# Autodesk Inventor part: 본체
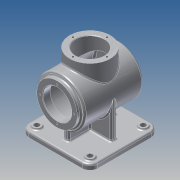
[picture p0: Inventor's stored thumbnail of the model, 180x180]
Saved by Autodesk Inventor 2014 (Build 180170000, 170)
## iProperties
Created: 2015-07
Part Number: 본체
Material: Aluminum 6061
Document SubType Name: Modeling
Designer: user
Density: 2.71 g/cm^3
Appearance: Aluminum - Flat
Mass: 1277.17 g
Surface Area: 1268.79 cm^2
Volume: 471.282 cm^3
Author: user
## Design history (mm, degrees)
sketch "Sketch1"
  geometry: C1 r 45 at (0, 0); 1 further point
  constraints: 1 centre point, 1 coincident
  dimensions: "d0" = 90 diameter of C1
extrude "Extrusion1" new body sketch "Sketch1" distance "d1" = 110; taper "d2" = 0 deg
workplane "Work Plane1"
sketch "Sketch4"
  geometry: L1 (45, 110)-(-45, 110) reference; L2 (-45, 0)-(45, 0) reference; L3 (45, 110)-(-45, 110) reference; L4 (-45, 0)-(45, 0) reference; L5 (-45, 0)-(-45, 110) reference; L6 (45, 0)-(45, 110) reference; L7 (0, 110)-(0, 0); C1 r 38 at (0, 55)
  constraints: 2 end point, 2 midpoint, 1 centre point
  dimensions: "d10" = 76 diameter of C1
extrude "Extrusion4" join sketch "Sketch4" stored distance "d11" = 96; taper "d12" = 0 deg
sketch "Sketch5"
  geometry: C1 r 38 at (0, 0) reference; C2 r 27 at (0, 0); 1 further point
  constraints: 1 centre point, 1 coincident
  dimensions: "d13" = 54 diameter of C2
extrude "Extrusion5" cut sketch "Sketch5" distance "d14" = 50.5; taper "d15" = 0 deg
sketch "Sketch6"
  geometry: C1 r 45 at (0, 0) reference; C2 r 38 at (0, 0)
  constraints: 1 centre point, 1 coincident
  dimensions: "d16" = 76 diameter of C2
extrude "Extrusion6" join sketch "Sketch6" distance "d17" = 7; taper "d18" = 0 deg
sketch "Sketch7"
  geometry: C1 r 38 at (0, 0) reference; C2 r 27 at (0, 0)
  constraints: 1 centre point, 1 coincident
  dimensions: "d19" = 54 diameter of C2
extrude "Extrusion7" cut sketch "Sketch7" distance "d20" = 14; taper "d21" = 0 deg
sketch "Sketch8"
  geometry: C1 r 27 at (0, 0) reference; C2 r 40 at (0, 0)
  constraints: 1 centre point, 1 coincident
  dimensions: "d22" = 80 diameter of C2
extrude "Extrusion8" cut sketch "Sketch8" distance "d23" = 96; taper "d24" = 0 deg
workplane "Work Plane2"
sketch "Sketch9"
  geometry: L1 (65, 120)-(-65, 120); L2 (-65, 120)-(-65, -10); L3 (-65, -10)-(65, -10); L4 (65, -10)-(65, 120); L5 (-45, 0)-(45, 0) reference; L6 (-65, 55)-(65, 55); L7 (45, 110)-(-45, 110) reference; L8 (0, 0)-(0, 110); 1 further point
  constraints: 12 end point, 5 midpoint, 1 parallel
  dimensions: "d26" = 130 distance of L1.start L1.end; "d27" = 130 distance of L1.end L2.end; "d28" = 10 distance between parallel lines of L5 L3; "d29" = 65 distance from line of point (0, 55) L2
extrude "Extrusion9" join sketch "Sketch9" distance "d30" = 10; taper "d31" = 0 deg
sketch "Sketch10"
  geometry: L1 (65, -120)-(65, 10) reference; L2 (65, 10)-(-65, 10) reference; L3 (-65, 10)-(-65, -120) reference; L4 (-65, -120)-(65, -120) reference; L5 (0, -120)-(0, 10); L6 (-65, -55)-(65, -55); L7 (-45, -60)-(45, -60); L8 (-45, -50)-(45, -50); L9 (-5, -100)-(-5, -10); L10 (5, -100)-(5, -10); L11 (-45, -60)-(-45, -50); L12 (-5, -100)-(5, -100); L13 (45, -60)-(45, -50); L14 (-5, -10)-(5, -10); 3 further points
  constraints: 20 end point, 7 parallel, 6 midpoint, 2 point on line
  dimensions: "d34" = 5 distance between parallel lines of L8 L6; "d35" = 10 distance between parallel lines of L8 L7; "d37" = 90 distance of L9.start L9.end; "d38" = 5 distance between parallel lines of L9 L5; "d39" = 10 distance between parallel lines of L10 L9; "d40" = 90 distance between parallel lines of L13 L11
extrude "Extrusion10" join sketch "Sketch10" stored distance "d41" = 10; taper "d42" = 0 deg
sketch "Sketch11"
  geometry: L1 (65, -120)-(65, 10) reference; L2 (65, 10)-(-65, 10) reference; L3 (-65, 10)-(-65, -120) reference; L4 (-65, -120)-(65, -120) reference; L5 (-65, -55)-(65, -55); L6 (0, -120)-(0, 10); C1 r 7.5 at (-50, -105); C2 r 7.5 at (-50, -5); C3 r 7.5 at (50, -105); C4 r 7.5 at (50, -5); 1 further point
  constraints: 4 centre point, 4 end point, 4 midpoint
  dimensions: "d43" = 15 diameter of C1; "d44" = 15 diameter of C2; "d45" = 50 distance from line of L5 C1.centre; "d46" = 100 distance of C2.centre C1.centre; "d47" = 50 distance from line of L6 C1.centre; "d48" = 50 distance from line of L6 C2.centre; "d49" = 50 distance from line of C3.centre L6; "d50" = 50 distance from line of C4.centre L6; "d51" = 50 distance from line of L5 C3.centre; "d52" = 100 distance of C4.centre C3.centre; "d53" = 15 diameter of C3; "d54" = 15 diameter of C4
extrude "Extrusion11" join sketch "Sketch11" distance "d55" = 3; taper "d56" = 0 deg
sketch "Sketch12"
  geometry: C1 r 7.5 at (0, 0) reference; C2 r 5 at (0, 0); 1 further point
  constraints: 1 centre point, 1 coincident
  dimensions: "d57" = 10 diameter of C2
extrude "Extrusion12" cut sketch "Sketch12" distance "d58" = 75.5; taper "d59" = 0 deg
sketch "Sketch13"
  geometry: C1 r 7.5 at (0, 0) reference; C2 r 5 at (0, 0); 1 further point
  constraints: 1 centre point, 1 coincident
  dimensions: "d60" = 10 diameter of C2
extrude "Extrusion13" cut sketch "Sketch13" distance "d61" = 75.5; taper "d62" = 0 deg
sketch "Sketch14"
  geometry: C1 r 7.5 at (0, 0) reference; C2 r 5 at (0, 0); 1 further point
  constraints: 1 centre point, 1 coincident
  dimensions: "d63" = 10 diameter of C2
extrude "Extrusion14" cut sketch "Sketch14" distance "d64" = 75.5; taper "d65" = 0 deg
sketch "Sketch15"
  geometry: C1 r 7.5 at (0, 0) reference; C2 r 5 at (0, 0); 1 further point
  constraints: 1 centre point, 1 coincident
  dimensions: "d66" = 10 diameter of C2
extrude "Extrusion15" cut sketch "Sketch15" distance "d67" = 75.5; taper "d68" = 0 deg
fillet "Fillet1" dims "d69" = 15
fillet "Fillet2" dims "d70" = 3
fillet "Fillet3" dims "d71" = 3
fillet "Fillet4" dims "d72" = 3
fillet "Fillet5" dims "d73" = 3
chamfer "Chamfer1" distance "d74" = 1; stored, may be unused: second distance "d75" = 2, angle "d76" = 45 deg
sketch "Sketch16" dims "d77" = 64
  geometry: C1 r 28 at (0, 0) reference; 2 further points
  constraints: 1 coincident, 1 vertical alignment, 2 other
hole "Hole1" sketch "Sketch16" at (0, 32) diameter "d78" = 3.459; stored, may be unused: countersink angle "d82" = 90 deg, drill point angle "d84" = 118 deg; dims "d79" = 8, "d80" = 4, "d81" = 2, "d83" = 10
pattern_circular "Circular Pattern1" dims angle "d86" = 360 deg
sketch "Sketch17" dims "d88" = 64
  geometry: C1 r 28 at (0, 0) reference; 3 further points
  constraints: 1 coincident, 1 vertical alignment, 2 other
hole "Hole2" sketch "Sketch17" at (0, 32) diameter "d89" = 3.459; stored, may be unused: countersink angle "d93" = 90 deg, drill point angle "d95" = 118 deg; dims "d90" = 8, "d91" = 4, "d92" = 2, "d94" = 10
pattern_circular "Circular Pattern2" dims angle "d97" = 360 deg
sketch "Sketch18"
  geometry: L1 (-24.887, 3.602)-(24.887, 3.602); L2 (24.887, 3.602)-(24.887, -3.602); L3 (24.887, -3.602)-(-24.887, -3.602); L4 (-24.887, -3.602)-(-24.887, 3.602); L5 (0, 3.602)-(0, -3.602); C1 r 42 at (0, 0) reference; 1 further point
  constraints: 3 midpoint, 2 end point, 1 coincident, 2 other
emboss "Emboss1" sketch "Sketch18" dims "d1" = 110, "d99" = 0.5, "d100" = 0
body "Solid1"
node "Projected Loop1"
other parameters: "d9" = 62, "d25" = -78
